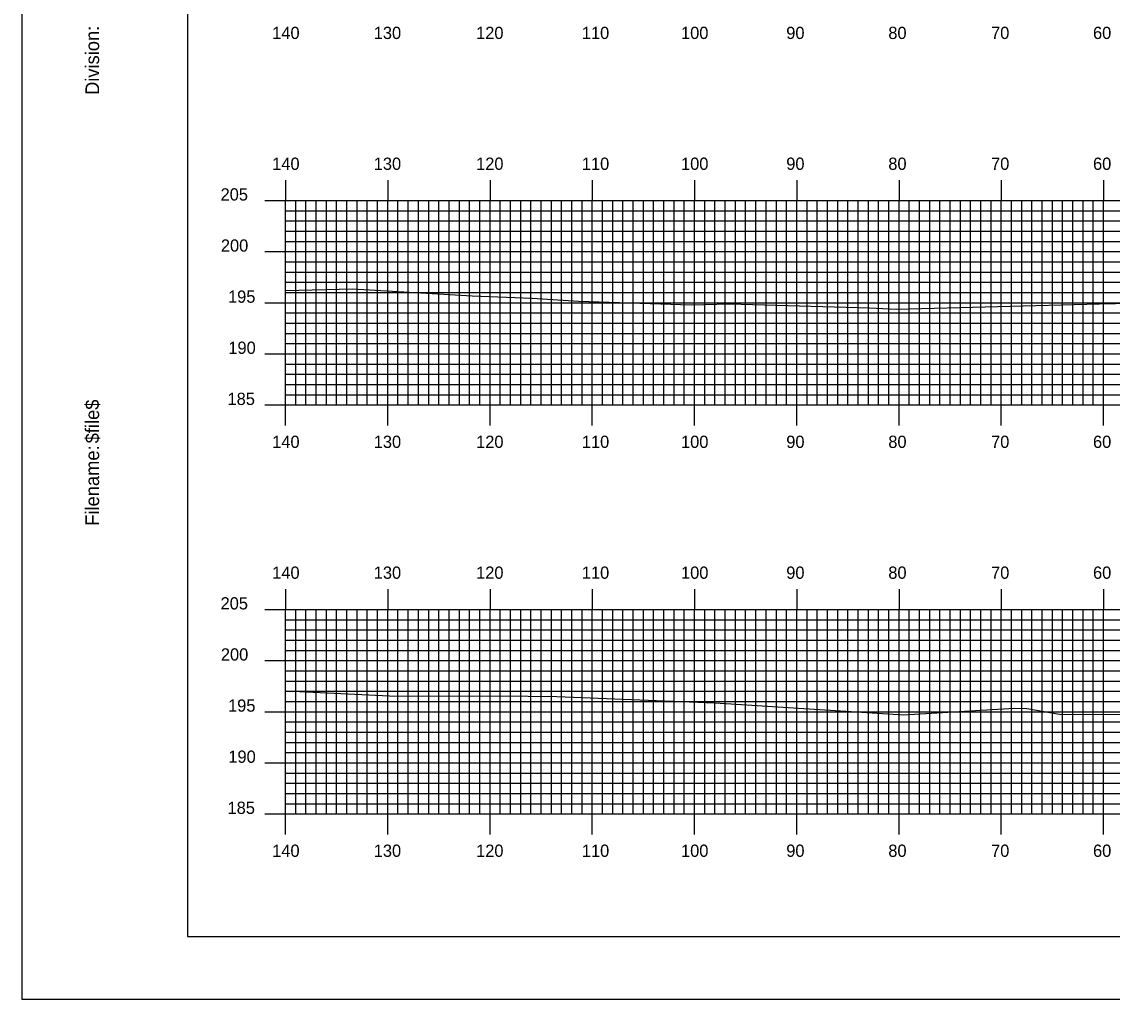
# Model space of a CAD drawing. Extents: x 1814522 to 1814865, y 442591 to 442811.
# Drawn here: x 1814521.7 to 1814628.4, y 442590.5 to 442686.2 of the extents above; entities that cross this region are included whole.
import ezdxf

# ---------------------------------------------------------------- set-up
doc = ezdxf.new("R2010")
doc.units = 0
for name, color, linetype in [('BORDER', 7, 'Continuous'), ('H_V ANNOTATION', 7, 'Continuous'), ('MAJOR', 7, 'Continuous'), ('MINOR', 7, 'Continuous'), ('PLOT BOUNDARY', 7, 'Continuous'), ('S_Roadway_Centerline', 7, 'Continuous')]:
    doc.layers.add(name, color=color, linetype=linetype)

msp = doc.modelspace()

# ---------------------------------------------------------------- linework, layer by layer
at = {"layer": 'BORDER'}
msp.add_lwpolyline([(1814537.91, 442596.67), (1814857.91, 442596.67), (1814857.91, 442806.67), (1814537.91, 442806.67)], close=True, dxfattribs=at)
at = {"layer": 'MAJOR'}
for p, q in [((1814547.51, 442670.67), (1814547.51, 442668.67)), ((1814557.51, 442670.67), (1814557.51, 442668.67)), ((1814567.51, 442670.67), (1814567.51, 442668.67)), ((1814577.51, 442670.67), (1814577.51, 442668.67)), ((1814587.51, 442670.67), (1814587.51, 442668.67)), ((1814597.51, 442670.67), (1814597.51, 442668.67)), ((1814607.51, 442670.67), (1814607.51, 442668.67)), ((1814617.51, 442670.67), (1814617.51, 442668.67)), ((1814627.51, 442670.67), (1814627.51, 442668.67)), ((1814545.5, 442668.67), (1814547.51, 442668.67)), ((1814547.51, 442668.67), (1814827.51, 442668.67)), ((1814547.51, 442648.67), (1814547.51, 442668.67)), ((1814547.51, 442648.67), (1814547.51, 442668.67)), ((1814547.51, 442668.67), (1814827.51, 442668.67)), ((1814557.51, 442648.67), (1814557.51, 442668.67)), ((1814567.51, 442648.67), (1814567.51, 442668.67)), ((1814577.51, 442648.67), (1814577.51, 442668.67)), ((1814587.51, 442648.67), (1814587.51, 442668.67)), ((1814597.51, 442648.67), (1814597.51, 442668.67)), ((1814607.51, 442648.67), (1814607.51, 442668.67)), ((1814617.51, 442648.67), (1814617.51, 442668.67)), ((1814627.51, 442648.67), (1814627.51, 442668.67)), ((1814545.5, 442663.67), (1814547.51, 442663.67)), ((1814547.51, 442663.67), (1814827.51, 442663.67)), ((1814545.5, 442658.67), (1814547.51, 442658.67)), ((1814547.51, 442658.67), (1814827.51, 442658.67)), ((1814545.5, 442653.67), (1814547.51, 442653.67)), ((1814547.51, 442653.67), (1814827.51, 442653.67)), ((1814545.5, 442648.67), (1814547.51, 442648.67)), ((1814547.51, 442648.67), (1814827.51, 442648.67)), ((1814547.51, 442648.67), (1814827.51, 442648.67)), ((1814547.51, 442646.66), (1814547.51, 442648.67)), ((1814557.51, 442646.66), (1814557.51, 442648.67)), ((1814567.51, 442646.66), (1814567.51, 442648.67)), ((1814577.51, 442646.66), (1814577.51, 442648.67)), ((1814587.51, 442646.66), (1814587.51, 442648.67)), ((1814597.51, 442646.66), (1814597.51, 442648.67)), ((1814607.51, 442646.66), (1814607.51, 442648.67)), ((1814617.51, 442646.66), (1814617.51, 442648.67)), ((1814627.51, 442646.66), (1814627.51, 442648.67)), ((1814547.51, 442630.67), (1814547.51, 442628.67)), ((1814557.51, 442630.67), (1814557.51, 442628.67)), ((1814567.51, 442630.67), (1814567.51, 442628.67)), ((1814577.51, 442630.67), (1814577.51, 442628.67)), ((1814587.51, 442630.67), (1814587.51, 442628.67)), ((1814597.51, 442630.67), (1814597.51, 442628.67)), ((1814607.51, 442630.67), (1814607.51, 442628.67)), ((1814617.51, 442630.67), (1814617.51, 442628.67)), ((1814627.51, 442630.67), (1814627.51, 442628.67)), ((1814545.5, 442628.67), (1814547.51, 442628.67)), ((1814547.51, 442628.67), (1814827.51, 442628.67)), ((1814547.51, 442608.67), (1814547.51, 442628.67)), ((1814547.51, 442608.67), (1814547.51, 442628.67)), ((1814547.51, 442628.67), (1814827.51, 442628.67)), ((1814557.51, 442608.67), (1814557.51, 442628.67)), ((1814567.51, 442608.67), (1814567.51, 442628.67)), ((1814577.51, 442608.67), (1814577.51, 442628.67)), ((1814587.51, 442608.67), (1814587.51, 442628.67)), ((1814597.51, 442608.67), (1814597.51, 442628.67)), ((1814607.51, 442608.67), (1814607.51, 442628.67)), ((1814617.51, 442608.67), (1814617.51, 442628.67)), ((1814627.51, 442608.67), (1814627.51, 442628.67)), ((1814545.5, 442623.67), (1814547.51, 442623.67)), ((1814547.51, 442623.67), (1814827.51, 442623.67)), ((1814545.5, 442618.67), (1814547.51, 442618.67)), ((1814547.51, 442618.67), (1814827.51, 442618.67)), ((1814545.5, 442613.67), (1814547.51, 442613.67)), ((1814547.51, 442613.67), (1814827.51, 442613.67)), ((1814545.5, 442608.67), (1814547.51, 442608.67)), ((1814547.51, 442608.67), (1814827.51, 442608.67)), ((1814547.51, 442608.67), (1814827.51, 442608.67)), ((1814547.51, 442606.66), (1814547.51, 442608.67)), ((1814557.51, 442606.66), (1814557.51, 442608.67)), ((1814567.51, 442606.66), (1814567.51, 442608.67)), ((1814577.51, 442606.66), (1814577.51, 442608.67)), ((1814587.51, 442606.66), (1814587.51, 442608.67)), ((1814597.51, 442606.66), (1814597.51, 442608.67)), ((1814607.51, 442606.66), (1814607.51, 442608.67)), ((1814617.51, 442606.66), (1814617.51, 442608.67)), ((1814627.51, 442606.66), (1814627.51, 442608.67))]:
    msp.add_line(p, q, dxfattribs=at)
at = {"layer": 'MINOR'}
for p, q in [((1814548.51, 442648.67), (1814548.51, 442668.67)), ((1814549.51, 442648.67), (1814549.51, 442668.67)), ((1814550.51, 442648.67), (1814550.51, 442668.67)), ((1814551.51, 442648.67), (1814551.51, 442668.67)), ((1814552.51, 442648.67), (1814552.51, 442668.67)), ((1814553.51, 442648.67), (1814553.51, 442668.67)), ((1814554.51, 442648.67), (1814554.51, 442668.67)), ((1814555.51, 442648.67), (1814555.51, 442668.67)), ((1814556.51, 442648.67), (1814556.51, 442668.67)), ((1814558.51, 442648.67), (1814558.51, 442668.67)), ((1814559.51, 442648.67), (1814559.51, 442668.67)), ((1814560.51, 442648.67), (1814560.51, 442668.67)), ((1814561.51, 442648.67), (1814561.51, 442668.67)), ((1814562.51, 442648.67), (1814562.51, 442668.67)), ((1814563.51, 442648.67), (1814563.51, 442668.67)), ((1814564.51, 442648.67), (1814564.51, 442668.67)), ((1814565.51, 442648.67), (1814565.51, 442668.67)), ((1814566.51, 442648.67), (1814566.51, 442668.67)), ((1814568.51, 442648.67), (1814568.51, 442668.67)), ((1814569.51, 442648.67), (1814569.51, 442668.67)), ((1814570.51, 442648.67), (1814570.51, 442668.67)), ((1814571.51, 442648.67), (1814571.51, 442668.67)), ((1814572.51, 442648.67), (1814572.51, 442668.67)), ((1814573.51, 442648.67), (1814573.51, 442668.67)), ((1814574.51, 442648.67), (1814574.51, 442668.67)), ((1814575.51, 442648.67), (1814575.51, 442668.67)), ((1814576.51, 442648.67), (1814576.51, 442668.67)), ((1814578.51, 442648.67), (1814578.51, 442668.67)), ((1814579.51, 442648.67), (1814579.51, 442668.67)), ((1814580.51, 442648.67), (1814580.51, 442668.67)), ((1814581.51, 442648.67), (1814581.51, 442668.67)), ((1814582.51, 442648.67), (1814582.51, 442668.67)), ((1814583.51, 442648.67), (1814583.51, 442668.67)), ((1814584.51, 442648.67), (1814584.51, 442668.67)), ((1814585.51, 442648.67), (1814585.51, 442668.67)), ((1814586.51, 442648.67), (1814586.51, 442668.67)), ((1814588.51, 442648.67), (1814588.51, 442668.67)), ((1814589.51, 442648.67), (1814589.51, 442668.67)), ((1814590.51, 442648.67), (1814590.51, 442668.67)), ((1814591.51, 442648.67), (1814591.51, 442668.67)), ((1814592.51, 442648.67), (1814592.51, 442668.67)), ((1814593.51, 442648.67), (1814593.51, 442668.67)), ((1814594.51, 442648.67), (1814594.51, 442668.67)), ((1814595.51, 442648.67), (1814595.51, 442668.67)), ((1814596.51, 442648.67), (1814596.51, 442668.67)), ((1814598.51, 442648.67), (1814598.51, 442668.67)), ((1814599.51, 442648.67), (1814599.51, 442668.67)), ((1814600.51, 442648.67), (1814600.51, 442668.67)), ((1814601.51, 442648.67), (1814601.51, 442668.67)), ((1814602.51, 442648.67), (1814602.51, 442668.67)), ((1814603.51, 442648.67), (1814603.51, 442668.67)), ((1814604.51, 442648.67), (1814604.51, 442668.67)), ((1814605.51, 442648.67), (1814605.51, 442668.67)), ((1814606.51, 442648.67), (1814606.51, 442668.67)), ((1814608.51, 442648.67), (1814608.51, 442668.67)), ((1814609.51, 442648.67), (1814609.51, 442668.67)), ((1814610.51, 442648.67), (1814610.51, 442668.67)), ((1814611.51, 442648.67), (1814611.51, 442668.67)), ((1814612.51, 442648.67), (1814612.51, 442668.67)), ((1814613.51, 442648.67), (1814613.51, 442668.67)), ((1814614.51, 442648.67), (1814614.51, 442668.67)), ((1814615.51, 442648.67), (1814615.51, 442668.67)), ((1814616.51, 442648.67), (1814616.51, 442668.67)), ((1814618.51, 442648.67), (1814618.51, 442668.67)), ((1814619.51, 442648.67), (1814619.51, 442668.67)), ((1814620.51, 442648.67), (1814620.51, 442668.67)), ((1814621.51, 442648.67), (1814621.51, 442668.67)), ((1814622.51, 442648.67), (1814622.51, 442668.67)), ((1814623.51, 442648.67), (1814623.51, 442668.67)), ((1814624.51, 442648.67), (1814624.51, 442668.67)), ((1814625.51, 442648.67), (1814625.51, 442668.67)), ((1814626.51, 442648.67), (1814626.51, 442668.67)), ((1814547.51, 442667.67), (1814827.51, 442667.67)), ((1814547.51, 442667.67), (1814549.51, 442667.67)), ((1814547.51, 442666.67), (1814827.51, 442666.67)), ((1814547.51, 442666.67), (1814549.51, 442666.67)), ((1814547.51, 442665.67), (1814827.51, 442665.67)), ((1814547.51, 442665.67), (1814549.51, 442665.67)), ((1814547.51, 442664.67), (1814827.51, 442664.67)), ((1814547.51, 442664.67), (1814549.51, 442664.67)), ((1814547.51, 442662.67), (1814827.51, 442662.67)), ((1814547.51, 442662.67), (1814549.51, 442662.67)), ((1814547.51, 442661.67), (1814827.51, 442661.67)), ((1814547.51, 442661.67), (1814549.51, 442661.67)), ((1814547.51, 442660.67), (1814827.51, 442660.67)), ((1814547.51, 442660.67), (1814549.51, 442660.67)), ((1814547.51, 442659.67), (1814827.51, 442659.67)), ((1814547.51, 442659.67), (1814549.51, 442659.67)), ((1814547.51, 442657.67), (1814827.51, 442657.67)), ((1814547.51, 442657.67), (1814549.51, 442657.67)), ((1814547.51, 442656.67), (1814827.51, 442656.67)), ((1814547.51, 442656.67), (1814549.51, 442656.67)), ((1814547.51, 442655.67), (1814827.51, 442655.67)), ((1814547.51, 442655.67), (1814549.51, 442655.67)), ((1814547.51, 442654.67), (1814827.51, 442654.67)), ((1814547.51, 442654.67), (1814549.51, 442654.67)), ((1814547.51, 442652.67), (1814827.51, 442652.67)), ((1814547.51, 442652.67), (1814549.51, 442652.67)), ((1814547.51, 442651.67), (1814827.51, 442651.67)), ((1814547.51, 442651.67), (1814549.51, 442651.67)), ((1814547.51, 442650.67), (1814827.51, 442650.67)), ((1814547.51, 442650.67), (1814549.51, 442650.67)), ((1814547.51, 442649.67), (1814827.51, 442649.67)), ((1814547.51, 442649.67), (1814549.51, 442649.67)), ((1814548.51, 442608.67), (1814548.51, 442628.67)), ((1814549.51, 442608.67), (1814549.51, 442628.67)), ((1814550.51, 442608.67), (1814550.51, 442628.67)), ((1814551.51, 442608.67), (1814551.51, 442628.67)), ((1814552.51, 442608.67), (1814552.51, 442628.67)), ((1814553.51, 442608.67), (1814553.51, 442628.67)), ((1814554.51, 442608.67), (1814554.51, 442628.67)), ((1814555.51, 442608.67), (1814555.51, 442628.67)), ((1814556.51, 442608.67), (1814556.51, 442628.67)), ((1814558.51, 442608.67), (1814558.51, 442628.67)), ((1814559.51, 442608.67), (1814559.51, 442628.67)), ((1814560.51, 442608.67), (1814560.51, 442628.67)), ((1814561.51, 442608.67), (1814561.51, 442628.67)), ((1814562.51, 442608.67), (1814562.51, 442628.67)), ((1814563.51, 442608.67), (1814563.51, 442628.67)), ((1814564.51, 442608.67), (1814564.51, 442628.67)), ((1814565.51, 442608.67), (1814565.51, 442628.67)), ((1814566.51, 442608.67), (1814566.51, 442628.67)), ((1814568.51, 442608.67), (1814568.51, 442628.67)), ((1814569.51, 442608.67), (1814569.51, 442628.67)), ((1814570.51, 442608.67), (1814570.51, 442628.67)), ((1814571.51, 442608.67), (1814571.51, 442628.67)), ((1814572.51, 442608.67), (1814572.51, 442628.67)), ((1814573.51, 442608.67), (1814573.51, 442628.67)), ((1814574.51, 442608.67), (1814574.51, 442628.67)), ((1814575.51, 442608.67), (1814575.51, 442628.67)), ((1814576.51, 442608.67), (1814576.51, 442628.67)), ((1814578.51, 442608.67), (1814578.51, 442628.67)), ((1814579.51, 442608.67), (1814579.51, 442628.67)), ((1814580.51, 442608.67), (1814580.51, 442628.67)), ((1814581.51, 442608.67), (1814581.51, 442628.67)), ((1814582.51, 442608.67), (1814582.51, 442628.67)), ((1814583.51, 442608.67), (1814583.51, 442628.67)), ((1814584.51, 442608.67), (1814584.51, 442628.67)), ((1814585.51, 442608.67), (1814585.51, 442628.67)), ((1814586.51, 442608.67), (1814586.51, 442628.67)), ((1814588.51, 442608.67), (1814588.51, 442628.67)), ((1814589.51, 442608.67), (1814589.51, 442628.67)), ((1814590.51, 442608.67), (1814590.51, 442628.67)), ((1814591.51, 442608.67), (1814591.51, 442628.67)), ((1814592.51, 442608.67), (1814592.51, 442628.67)), ((1814593.51, 442608.67), (1814593.51, 442628.67)), ((1814594.51, 442608.67), (1814594.51, 442628.67)), ((1814595.51, 442608.67), (1814595.51, 442628.67)), ((1814596.51, 442608.67), (1814596.51, 442628.67)), ((1814598.51, 442608.67), (1814598.51, 442628.67)), ((1814599.51, 442608.67), (1814599.51, 442628.67)), ((1814600.51, 442608.67), (1814600.51, 442628.67)), ((1814601.51, 442608.67), (1814601.51, 442628.67)), ((1814602.51, 442608.67), (1814602.51, 442628.67)), ((1814603.51, 442608.67), (1814603.51, 442628.67)), ((1814604.51, 442608.67), (1814604.51, 442628.67)), ((1814605.51, 442608.67), (1814605.51, 442628.67)), ((1814606.51, 442608.67), (1814606.51, 442628.67)), ((1814608.51, 442608.67), (1814608.51, 442628.67)), ((1814609.51, 442608.67), (1814609.51, 442628.67)), ((1814610.51, 442608.67), (1814610.51, 442628.67)), ((1814611.51, 442608.67), (1814611.51, 442628.67)), ((1814612.51, 442608.67), (1814612.51, 442628.67)), ((1814613.51, 442608.67), (1814613.51, 442628.67)), ((1814614.51, 442608.67), (1814614.51, 442628.67)), ((1814615.51, 442608.67), (1814615.51, 442628.67)), ((1814616.51, 442608.67), (1814616.51, 442628.67)), ((1814618.51, 442608.67), (1814618.51, 442628.67)), ((1814619.51, 442608.67), (1814619.51, 442628.67)), ((1814620.51, 442608.67), (1814620.51, 442628.67)), ((1814621.51, 442608.67), (1814621.51, 442628.67)), ((1814622.51, 442608.67), (1814622.51, 442628.67)), ((1814623.51, 442608.67), (1814623.51, 442628.67)), ((1814624.51, 442608.67), (1814624.51, 442628.67)), ((1814625.51, 442608.67), (1814625.51, 442628.67)), ((1814626.51, 442608.67), (1814626.51, 442628.67)), ((1814547.51, 442627.67), (1814827.51, 442627.67)), ((1814547.51, 442627.67), (1814549.51, 442627.67)), ((1814547.51, 442626.67), (1814827.51, 442626.67)), ((1814547.51, 442626.67), (1814549.51, 442626.67)), ((1814547.51, 442625.67), (1814827.51, 442625.67)), ((1814547.51, 442625.67), (1814549.51, 442625.67)), ((1814547.51, 442624.67), (1814827.51, 442624.67)), ((1814547.51, 442624.67), (1814549.51, 442624.67)), ((1814547.51, 442622.67), (1814827.51, 442622.67)), ((1814547.51, 442622.67), (1814549.51, 442622.67)), ((1814547.51, 442621.67), (1814827.51, 442621.67)), ((1814547.51, 442621.67), (1814549.51, 442621.67)), ((1814547.51, 442620.67), (1814827.51, 442620.67)), ((1814547.51, 442620.67), (1814549.51, 442620.67)), ((1814547.51, 442619.67), (1814827.51, 442619.67)), ((1814547.51, 442619.67), (1814549.51, 442619.67)), ((1814547.51, 442617.67), (1814827.51, 442617.67)), ((1814547.51, 442617.67), (1814549.51, 442617.67)), ((1814547.51, 442616.67), (1814827.51, 442616.67)), ((1814547.51, 442616.67), (1814549.51, 442616.67)), ((1814547.51, 442615.67), (1814827.51, 442615.67)), ((1814547.51, 442615.67), (1814549.51, 442615.67)), ((1814547.51, 442614.67), (1814827.51, 442614.67)), ((1814547.51, 442614.67), (1814549.51, 442614.67)), ((1814547.51, 442612.67), (1814827.51, 442612.67)), ((1814547.51, 442612.67), (1814549.51, 442612.67)), ((1814547.51, 442611.67), (1814827.51, 442611.67)), ((1814547.51, 442611.67), (1814549.51, 442611.67)), ((1814547.51, 442610.67), (1814827.51, 442610.67)), ((1814547.51, 442610.67), (1814549.51, 442610.67)), ((1814547.51, 442609.67), (1814827.51, 442609.67)), ((1814547.51, 442609.67), (1814549.51, 442609.67))]:
    msp.add_line(p, q, dxfattribs=at)
at = {"layer": 'PLOT BOUNDARY'}
msp.add_lwpolyline([(1814521.72, 442590.55), (1814861.72, 442590.55), (1814861.72, 442810.55), (1814521.72, 442810.55)], close=True, dxfattribs=at)
at = {"layer": 'S_Roadway_Centerline'}
for points in [[(1814547.51, 442659.88), (1814554.06, 442660.02), (1814565.76, 442659.35), (1814571.63, 442659.13), (1814576.17, 442658.83), (1814587.17, 442658.47), (1814590.92, 442658.57), (1814604.61, 442658.16), (1814607.23, 442658.03), (1814627.1, 442658.56), (1814636.48, 442658.76), (1814637.55, 442658.76), (1814651.16, 442658.44), (1814652.19, 442658.44), (1814667.03, 442658.69), (1814669.78, 442658.65), (1814672.93, 442658.72), (1814684.86, 442658.34), (1814697.63, 442658.11), (1814701.77, 442658.13), (1814707.31, 442658.17), (1814719.86, 442658.3), (1814727.24, 442658.44), (1814735.31, 442658.05)], [(1814547.51, 442620.72), (1814557.69, 442620.22), (1814571.23, 442620.2), (1814574.03, 442620.14), (1814589.47, 442619.53), (1814590.56, 442619.48), (1814598.19, 442618.98), (1814607.94, 442618.36), (1814618.8, 442619.02), (1814620.02, 442618.98), (1814623.21, 442618.44), (1814639.27, 442618.39)]]:
    msp.add_lwpolyline(points, dxfattribs=at)

# ---------------------------------------------------------------- texts
at = {"layer": 'BORDER'}
for s, p in [('Division:', (1814529.28, 442679)), ('$file$', (1814529.28, 442644.92)), ('Filename:', (1814529.28, 442636.86))]:
    msp.add_text(s, height=1.339, rotation=90, dxfattribs=at).set_placement(p)
at = {"layer": 'H_V ANNOTATION'}
for s, p in [('140', (1814546.21, 442684.47)), ('130', (1814556.14, 442684.47)), ('120', (1814566.15, 442684.47)), ('110', (1814576.49, 442684.47)), ('100', (1814586.19, 442684.47)), ('90', (1814596.48, 442684.47)), ('80', (1814606.46, 442684.47)), ('70', (1814616.51, 442684.47)), ('60', (1814626.48, 442684.47)), ('140', (1814546.21, 442671.67)), ('130', (1814556.14, 442671.67)), ('120', (1814566.15, 442671.67)), ('110', (1814576.49, 442671.67)), ('100', (1814586.19, 442671.67)), ('90', (1814596.48, 442671.67)), ('80', (1814606.46, 442671.67)), ('70', (1814616.51, 442671.67)), ('60', (1814626.48, 442671.67)), ('205', (1814541.16, 442668.67)), ('200', (1814541.19, 442663.67)), ('195', (1814541.89, 442658.67)), ('190', (1814541.92, 442653.67)), ('185', (1814541.84, 442648.67)), ('140', (1814546.21, 442644.47)), ('130', (1814556.14, 442644.47)), ('120', (1814566.15, 442644.47)), ('110', (1814576.49, 442644.47)), ('100', (1814586.19, 442644.47)), ('90', (1814596.48, 442644.47)), ('80', (1814606.46, 442644.47)), ('70', (1814616.51, 442644.47)), ('60', (1814626.48, 442644.47)), ('140', (1814546.21, 442631.67)), ('130', (1814556.14, 442631.67)), ('120', (1814566.15, 442631.67)), ('110', (1814576.49, 442631.67)), ('100', (1814586.19, 442631.67)), ('90', (1814596.48, 442631.67)), ('80', (1814606.46, 442631.67)), ('70', (1814616.51, 442631.67)), ('60', (1814626.48, 442631.67)), ('205', (1814541.16, 442628.67)), ('200', (1814541.19, 442623.67)), ('195', (1814541.89, 442618.67)), ('190', (1814541.92, 442613.67)), ('185', (1814541.84, 442608.67)), ('140', (1814546.21, 442604.47)), ('130', (1814556.14, 442604.47)), ('120', (1814566.15, 442604.47)), ('110', (1814576.49, 442604.47)), ('100', (1814586.19, 442604.47)), ('90', (1814596.48, 442604.47)), ('80', (1814606.46, 442604.47)), ('70', (1814616.51, 442604.47)), ('60', (1814626.48, 442604.47))]:
    msp.add_text(s, height=1.2, dxfattribs=at).set_placement(p)
at = {"layer": 'MAJOR'}
for p in [(1814547.5, 442648.67), (1814547.5, 442608.67)]:
    msp.add_text('-', height=0.012, dxfattribs=at).set_placement(p)

doc.saveas('drawing.dxf')
